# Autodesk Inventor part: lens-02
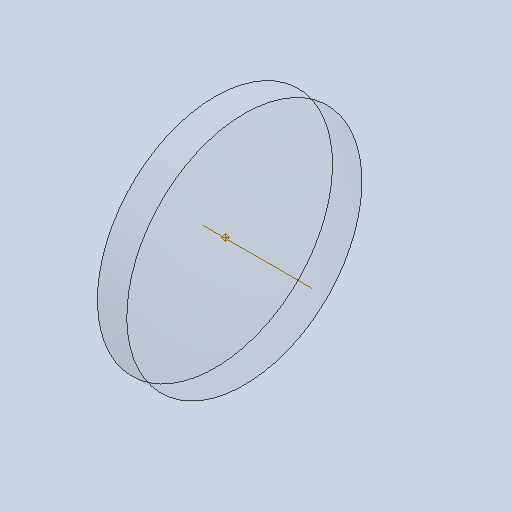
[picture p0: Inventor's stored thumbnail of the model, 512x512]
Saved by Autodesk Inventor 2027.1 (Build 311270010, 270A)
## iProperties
Created: 2026-07
Part Number: lens-02
Material: Generic
Document SubType Name: Modeling
Designer: dunge
Density: 1 g/cm^3
Appearance: Default
Author: dunge
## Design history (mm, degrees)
sketch "Sketch1"
  geometry: L1 (-3.175, 0)-(0, 0); L2 (-1.27, 15.24)-(0, 15.24); L3 (0, 15.24)-(0, 0); L4 (2.54, 15.24)-(0, 15.24); L5 (5.842, 0)-(0, 0); L6 (-257.62, 0)-(421.132, 0) reference; A1 r 61.913 centre (58.738, 0) between (-1.27, 15.24) and (-3.175, 0); A2 r 36.82 centre (-30.978, 0) between (5.842, 0) and (2.54, 15.24)
  constraints: 10 end point, 4 point on circle, 3 horizontal, 2 centre point, 2 line through centre, 1 perpendicular, 1 point on line
  dimensions: "SIDE_2_MINOR" = 1.27 distance of L2.start L2.end; "LENS_RADIUS" = 15.24 distance of L2.end L1.end; "SIDE_1_MINOR" = 2.54 distance of L4.start L2.end; "SIDE_1_MAJOR" = 5.842 distance of L5.start L1.end; "SIDE_2_MAJOR" = 3.175 distance of L1.start L1.end
revolve "Revolution1" sketch "Sketch1" stored, may be unused: angle "d3" = 90 deg
workpoint "Work Point2"
  workaxis "Work Axis1"
node "Lens"
node "Finishes"
node "Finish1" dims "Finish1_Area" = 186.98013
